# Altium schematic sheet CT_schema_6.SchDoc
size 274 x 160 mm
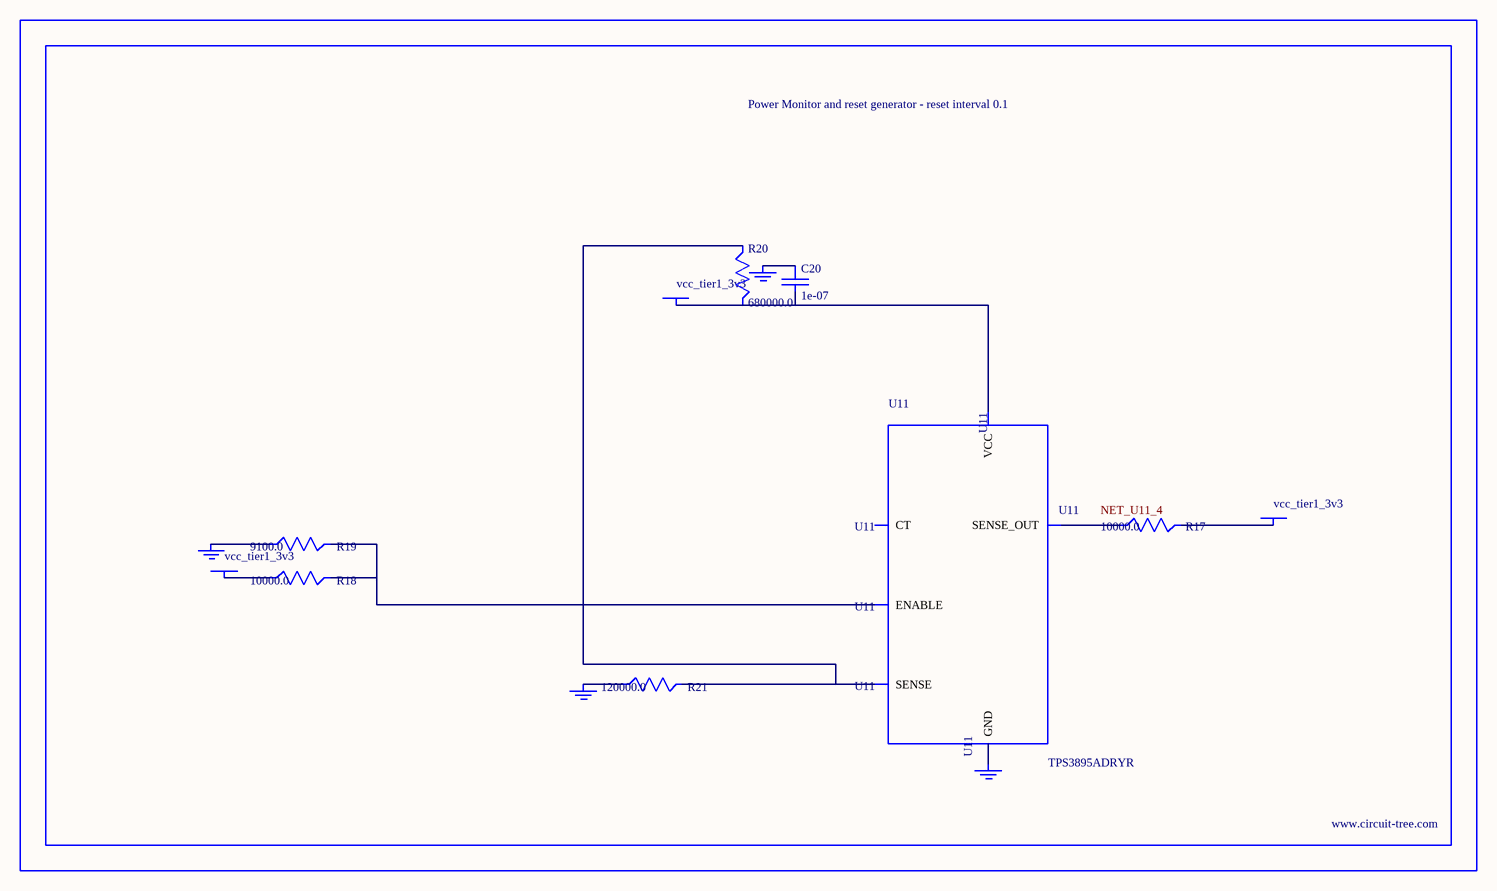
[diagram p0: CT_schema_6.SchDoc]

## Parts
BORDER5  (no value)
C20  1e-07  [C0402]
GND_INSTANCE_5_0  (no value)
GND_INSTANCE_5_1  (no value)
GND_INSTANCE_5_2  (no value)
GND_INSTANCE_5_3  (no value)
POWER_INSTANCE_5_0  vcc_tier1_3v3
POWER_INSTANCE_5_1  vcc_tier1_3v3
POWER_INSTANCE_5_2  vcc_tier1_3v3
R17  10000.0  [R0603]
R18  10000.0  [R0603]
R19  9100.0  [R0603]
R20  680000.0  [R0603]
R21  120000.0  [R0603]
U11  TPS3895ADRYR  [SON-6]

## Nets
NetC20_1: C20.1 GND_INSTANCE_5_2.0(GND)
NetC20_2: C20.2 POWER_INSTANCE_5_2.0(PWR) R20.2 U11.6(VCC)
NetGND_INSTANCE_5_0_0: GND_INSTANCE_5_0.0(GND) R19.1
NetGND_INSTANCE_5_1_0: GND_INSTANCE_5_1.0(GND) R21.1
NetGND_INSTANCE_5_3_0: GND_INSTANCE_5_3.0(GND) U11.2(GND)
NetPOWER_INSTANCE_5_0_0: POWER_INSTANCE_5_0.0(PWR) R18.1
NetPOWER_INSTANCE_5_1_0: POWER_INSTANCE_5_1.0(PWR) R17.2
NetR17_1: R17.1 U11.4(SENSE_OUT)
NetR18_2: R18.2 R19.2 U11.1(ENABLE)
NetR20_1: R20.1 R21.2 U11.3(SENSE)

Not connected (* = marked no-connect by the designer): U11 5(CT)

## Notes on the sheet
- Labels drawn without touching a wire or pin: NET_U11_4

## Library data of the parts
BORDER5 = BORDER_PAGE5
C20 = C0402C104K3RACTU
GND_INSTANCE_5_0-GND_INSTANCE_5_3 = GND
POWER_INSTANCE_5_0-POWER_INSTANCE_5_2 = PWR
R17 R18 = RC0603JR-0710KL
R19 = RC0603JR-079K1L
R20 = RC0603JR-07680KL
R21 = RC0603JR-07120KL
